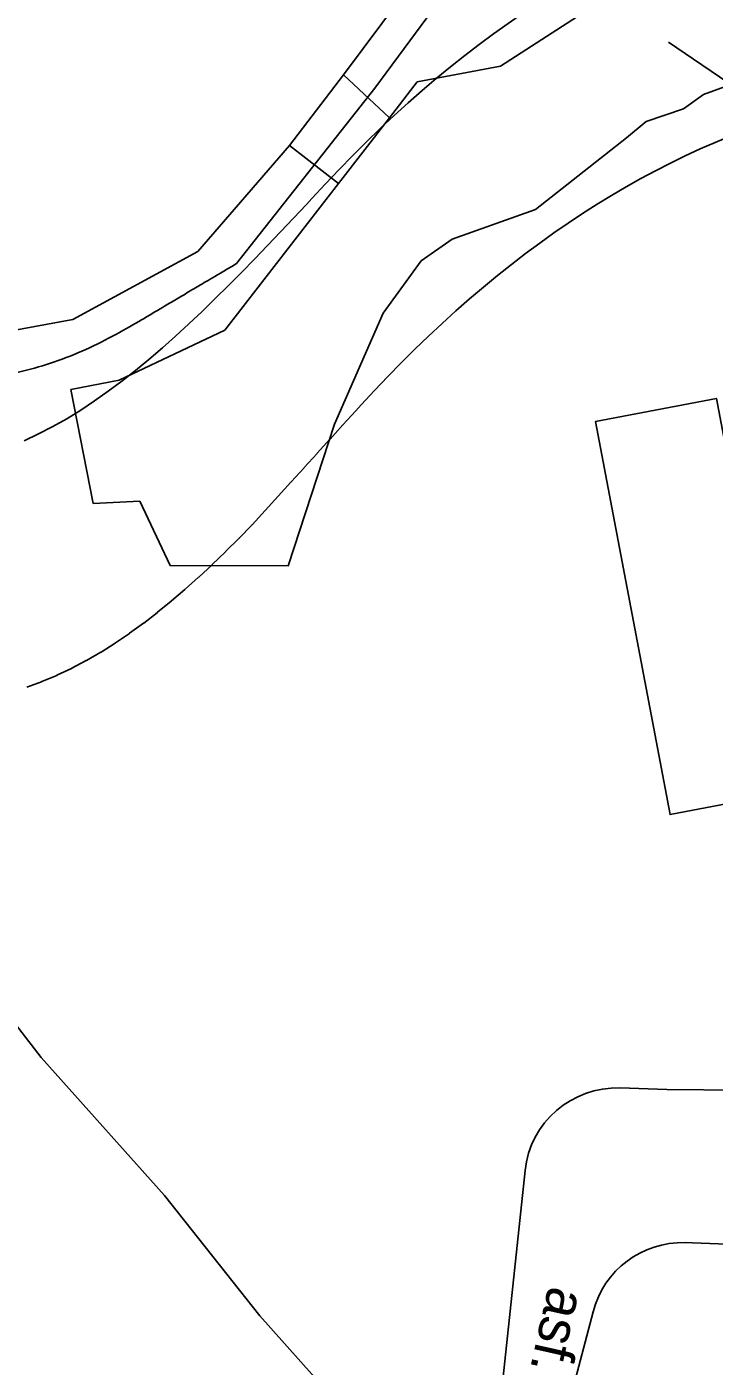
# Model space of a CAD drawing. Extents: x 6541740 to 6566395, y 5525066 to 5530361.
# Drawn here: x 6557403.94 to 6557426.25, y 5526125.72 to 5526169.2 of the extents above; entities that cross this region are included whole.
import ezdxf

# ---------------------------------------------------------------- set-up
doc = ezdxf.new("R2010")
doc.units = 0
for name, color, linetype in [('Domyślna', 7, 'Continuous'), ('ps_wymiarowanie', 7, 'Continuous'), ('TOR_PRZEK_P-teren istniejacy', 7, 'Continuous'), ('TOR_PRZEK_P-uklad odniesienia', 7, 'Continuous'), ('TOR_PS_OPIS_T-symbole geometrii', 7, 'Continuous'), ('TOR_PS_T-rowy otwarte nieumocnione', 7, 'Continuous'), ('TOR_PS_T-wypelnienia', 7, 'Continuous')]:
    doc.layers.add(name, color=color, linetype=linetype)

msp = doc.modelspace()

# ---------------------------------------------------------------- linework, layer by layer
at = {"layer": 'Domyślna'}
for p, q in [((6557413.194, 5526163.62), (6557413.023, 5526163.432)), ((6557413.194, 5526163.62), (6557413.023, 5526163.432)), ((6557414.793, 5526156.921), (6557414.622, 5526156.734)), ((6557414.793, 5526156.921), (6557414.622, 5526156.734))]:
    msp.add_line(p, q, dxfattribs=at)
at = {"layer": 'ps_wymiarowanie'}
for p, q in [((6557412.466, 5526165.343), (6557409.491, 5526161.9)), ((6557412.466, 5526165.343), (6557409.491, 5526161.9)), ((6557409.491, 5526161.9), (6557405.44, 5526159.699)), ((6557409.491, 5526161.9), (6557405.44, 5526159.699)), ((6557386.306, 5526156.188), (6557405.44, 5526159.699)), ((6557386.306, 5526156.188), (6557405.44, 5526159.699)), ((6557406.094, 5526153.721), (6557405.378, 5526157.421)), ((6557406.094, 5526153.721), (6557405.378, 5526157.421)), ((6557424.715, 5526134.701), (6557423.197, 5526134.753)), ((6557424.715, 5526134.701), (6557423.197, 5526134.753)), ((6557427.102, 5526134.683), (6557424.715, 5526134.701)), ((6557427.102, 5526134.683), (6557424.715, 5526134.701)), ((6557420.112, 5526132.071), (6557419.369, 5526125.077)), ((6557420.112, 5526132.071), (6557419.369, 5526125.077)), ((6557425.301, 5526129.733), (6557425.539, 5526129.726)), ((6557425.301, 5526129.733), (6557425.539, 5526129.726)), ((6557425.539, 5526129.726), (6557428.031, 5526129.638)), ((6557425.539, 5526129.726), (6557428.031, 5526129.638)), ((6557421.042, 5526122.606), (6557422.317, 5526127.491)), ((6557421.042, 5526122.606), (6557422.317, 5526127.491))]:
    msp.add_line(p, q, dxfattribs=at)
for points in [[(6557466.511, 5526187.683), (6557465.043, 5526186.988), (6557461.423, 5526185.275), (6557456.522, 5526180.201), (6557454.61, 5526178.451), (6557453.626, 5526177.55), (6557452.528, 5526176.764), (6557450.12, 5526175.708), (6557447.799, 5526174.9), (6557447.318, 5526174.77), (6557446.173, 5526174.319), (6557442.253, 5526172.787), (6557436.476, 5526171.057), (6557431.225, 5526168.935), (6557425.9, 5526167), (6557425.249, 5526166.537), (6557424.035, 5526166.119), (6557423.401, 5526165.589)], [(6557466.511, 5526187.683), (6557465.043, 5526186.988), (6557461.423, 5526185.275), (6557456.522, 5526180.201), (6557454.61, 5526178.451), (6557453.626, 5526177.55), (6557452.528, 5526176.764), (6557450.12, 5526175.708), (6557447.799, 5526174.9), (6557447.318, 5526174.77), (6557446.173, 5526174.319), (6557442.253, 5526172.787), (6557436.476, 5526171.057), (6557431.225, 5526168.935), (6557425.9, 5526167), (6557425.249, 5526166.537), (6557424.035, 5526166.119), (6557423.401, 5526165.589)], [(6557414.217, 5526167.638), (6557417.983, 5526172.683)], [(6557414.217, 5526167.638), (6557417.983, 5526172.683)], [(6557422.48, 5526169.958), (6557419.312, 5526167.917), (6557416.615, 5526167.404), (6557415.709, 5526166.237)], [(6557422.48, 5526169.958), (6557419.312, 5526167.917), (6557416.615, 5526167.404), (6557415.709, 5526166.237)], [(6557412.466, 5526165.343), (6557414.056, 5526164.107), (6557415.709, 5526166.237), (6557414.217, 5526167.638), (6557412.466, 5526165.343)], [(6557412.466, 5526165.343), (6557414.056, 5526164.107), (6557415.709, 5526166.237), (6557414.217, 5526167.638), (6557412.466, 5526165.343)], [(6557423.401, 5526165.589), (6557420.451, 5526163.263), (6557417.742, 5526162.298), (6557416.741, 5526161.601), (6557415.504, 5526159.901), (6557413.933, 5526156.294), (6557412.424, 5526151.696), (6557408.592, 5526151.709), (6557407.609, 5526153.795), (6557406.094, 5526153.721)], [(6557423.401, 5526165.589), (6557420.451, 5526163.263), (6557417.742, 5526162.298), (6557416.741, 5526161.601), (6557415.504, 5526159.901), (6557413.933, 5526156.294), (6557412.424, 5526151.696), (6557408.592, 5526151.709), (6557407.609, 5526153.795), (6557406.094, 5526153.721)], [(6557414.056, 5526164.107), (6557410.366, 5526159.352), (6557406.94, 5526157.723), (6557405.378, 5526157.421)], [(6557414.056, 5526164.107), (6557410.366, 5526159.352), (6557406.94, 5526157.723), (6557405.378, 5526157.421)]]:
    msp.add_lwpolyline(points, dxfattribs=at)
msp.add_lwpolyline([(6557428.739, 5526144.373), (6557424.817, 5526143.629), (6557422.398, 5526156.387), (6557426.32, 5526157.131)], close=True, dxfattribs=at)
msp.add_lwpolyline([(6557428.739, 5526144.373), (6557424.817, 5526143.629), (6557422.398, 5526156.387), (6557426.32, 5526157.131)], close=True, dxfattribs=at)
at = {"layer": 'TOR_PRZEK_P-uklad odniesienia'}
msp.add_line((6557434.581, 5526162.007), (6557424.762, 5526168.697), dxfattribs=at)
msp.add_line((6557434.581, 5526162.007), (6557424.762, 5526168.697), dxfattribs=at)
at = {"layer": 'TOR_PS_OPIS_T-symbole geometrii'}
for p, q in [((6557414.622, 5526156.734), (6557414.202, 5526156.272)), ((6557414.622, 5526156.734), (6557414.202, 5526156.272)), ((6557414.201, 5526156.271), (6557413.782, 5526155.81)), ((6557414.201, 5526156.271), (6557413.782, 5526155.81)), ((6557413.781, 5526155.809), (6557413.364, 5526155.352)), ((6557413.781, 5526155.809), (6557413.364, 5526155.352)), ((6557413.363, 5526155.35), (6557412.94, 5526154.886)), ((6557413.363, 5526155.35), (6557412.94, 5526154.886)), ((6557412.939, 5526154.884), (6557412.518, 5526154.421)), ((6557412.939, 5526154.884), (6557412.518, 5526154.421)), ((6557412.516, 5526154.419), (6557412.097, 5526153.959)), ((6557412.516, 5526154.419), (6557412.097, 5526153.959)), ((6557412.095, 5526153.956), (6557411.676, 5526153.496)), ((6557412.095, 5526153.956), (6557411.676, 5526153.496)), ((6557411.673, 5526153.493), (6557411.255, 5526153.033)), ((6557411.673, 5526153.493), (6557411.255, 5526153.033)), ((6557411.252, 5526153.03), (6557410.828, 5526152.589)), ((6557411.252, 5526153.03), (6557410.828, 5526152.589)), ((6557410.824, 5526152.585), (6557410.396, 5526152.16)), ((6557410.824, 5526152.585), (6557410.396, 5526152.16)), ((6557410.392, 5526152.156), (6557409.961, 5526151.742)), ((6557410.392, 5526152.156), (6557409.961, 5526151.742)), ((6557409.957, 5526151.737), (6557409.524, 5526151.335)), ((6557409.957, 5526151.737), (6557409.524, 5526151.335)), ((6557409.519, 5526151.33), (6557409.083, 5526150.94)), ((6557409.519, 5526151.33), (6557409.083, 5526150.94)), ((6557409.077, 5526150.936), (6557408.638, 5526150.56)), ((6557409.077, 5526150.936), (6557408.638, 5526150.56)), ((6557408.183, 5526150.189), (6557407.737, 5526149.844)), ((6557408.183, 5526150.189), (6557407.737, 5526149.844)), ((6557408.632, 5526150.555), (6557408.189, 5526150.194)), ((6557408.632, 5526150.555), (6557408.189, 5526150.194)), ((6557407.73, 5526149.839), (6557407.28, 5526149.512)), ((6557407.73, 5526149.839), (6557407.28, 5526149.512)), ((6557407.273, 5526149.507), (6557406.818, 5526149.198)), ((6557407.273, 5526149.507), (6557406.818, 5526149.198)), ((6557406.344, 5526148.898), (6557405.881, 5526148.629)), ((6557406.344, 5526148.898), (6557405.881, 5526148.629)), ((6557406.811, 5526149.192), (6557406.352, 5526148.903)), ((6557406.811, 5526149.192), (6557406.352, 5526148.903)), ((6557405.872, 5526148.624), (6557405.405, 5526148.376)), ((6557405.872, 5526148.624), (6557405.405, 5526148.376)), ((6557404.914, 5526148.142), (6557404.437, 5526147.941)), ((6557404.914, 5526148.142), (6557404.437, 5526147.941)), ((6557405.396, 5526148.371), (6557404.924, 5526148.147)), ((6557405.396, 5526148.371), (6557404.924, 5526148.147)), ((6557404.426, 5526147.937), (6557403.944, 5526147.762)), ((6557404.426, 5526147.937), (6557403.944, 5526147.762))]:
    msp.add_line(p, q, dxfattribs=at)
msp.add_lwpolyline([(6557413.023, 5526163.432), (6557412.6, 5526162.985), (6557412.178, 5526162.54), (6557411.755, 5526162.097), (6557411.333, 5526161.658), (6557410.909, 5526161.223), (6557410.485, 5526160.794), (6557410.059, 5526160.372), (6557409.633, 5526159.958), (6557409.204, 5526159.552), (6557408.774, 5526159.157), (6557408.342, 5526158.772), (6557407.908, 5526158.4), (6557407.471, 5526158.04), (6557407.031, 5526157.695), (6557406.589, 5526157.365), (6557406.143, 5526157.051), (6557405.695, 5526156.755), (6557405.242, 5526156.476), (6557404.787, 5526156.218), (6557404.327, 5526155.979), (6557403.863, 5526155.762)], dxfattribs=at)
msp.add_lwpolyline([(6557413.023, 5526163.432), (6557412.6, 5526162.985), (6557412.178, 5526162.54), (6557411.755, 5526162.097), (6557411.333, 5526161.658), (6557410.909, 5526161.223), (6557410.485, 5526160.794), (6557410.059, 5526160.372), (6557409.633, 5526159.958), (6557409.204, 5526159.552), (6557408.774, 5526159.157), (6557408.342, 5526158.772), (6557407.908, 5526158.4), (6557407.471, 5526158.04), (6557407.031, 5526157.695), (6557406.589, 5526157.365), (6557406.143, 5526157.051), (6557405.695, 5526156.755), (6557405.242, 5526156.476), (6557404.787, 5526156.218), (6557404.327, 5526155.979), (6557403.863, 5526155.762)], dxfattribs=at)
for centre, major_axis, start_param, end_param in [((6557505.371, 5525777.489), (-75.146, 396.441), 0.018415, 0.185981), ((6557505.371, 5525777.489), (-75.146, 396.441), 0.018415, 0.185981), ((6557505.371, 5525777.489), (-73.843, 389.563), 0.018415, 0.185981), ((6557505.371, 5525777.489), (-73.843, 389.563), 0.018415, 0.185981), ((6557413.398, 5526159.616), (0.652, -3.439), 0.191609, 0.192157), ((6557413.398, 5526159.616), (0.652, -3.439), 0.191609, 0.192157), ((6557412.978, 5526159.155), (0.652, -3.439), 0.190513, 0.191609), ((6557412.978, 5526159.155), (0.652, -3.439), 0.190513, 0.191609), ((6557412.562, 5526158.697), (0.652, -3.439), 0.18887, 0.190513), ((6557412.562, 5526158.697), (0.652, -3.439), 0.18887, 0.190513), ((6557412.139, 5526158.233), (0.652, -3.439), 0.186679, 0.18887), ((6557412.139, 5526158.233), (0.652, -3.439), 0.186679, 0.18887), ((6557411.718, 5526157.77), (0.652, -3.439), 0.183939, 0.186679), ((6557411.718, 5526157.77), (0.652, -3.439), 0.183939, 0.186679), ((6557411.299, 5526157.31), (0.652, -3.439), 0.180652, 0.183939), ((6557411.299, 5526157.31), (0.652, -3.439), 0.180652, 0.183939), ((6557410.88, 5526156.849), (0.652, -3.439), 0.176817, 0.180652), ((6557410.88, 5526156.849), (0.652, -3.439), 0.176817, 0.180652), ((6557410.462, 5526156.39), (0.652, -3.439), 0.172435, 0.176817), ((6557410.462, 5526156.39), (0.652, -3.439), 0.172435, 0.176817), ((6557410.038, 5526155.949), (0.652, -3.439), 0.167504, 0.172435), ((6557410.038, 5526155.949), (0.652, -3.439), 0.167504, 0.172435), ((6557409.61, 5526155.523), (0.652, -3.439), 0.162026, 0.167504), ((6557409.61, 5526155.523), (0.652, -3.439), 0.162026, 0.167504), ((6557409.179, 5526155.109), (0.652, -3.439), 0.155999, 0.162026), ((6557409.179, 5526155.109), (0.652, -3.439), 0.155999, 0.162026), ((6557408.746, 5526154.706), (0.652, -3.439), 0.149425, 0.155999), ((6557408.746, 5526154.706), (0.652, -3.439), 0.149425, 0.155999), ((6557408.31, 5526154.317), (0.652, -3.439), 0.142303, 0.149425), ((6557408.31, 5526154.317), (0.652, -3.439), 0.142303, 0.149425), ((6557407.428, 5526153.58), (0.652, -3.439), 0.126416, 0.134633), ((6557407.428, 5526153.58), (0.652, -3.439), 0.126416, 0.134633), ((6557407.871, 5526153.941), (0.652, -3.439), 0.134633, 0.142303), ((6557407.871, 5526153.941), (0.652, -3.439), 0.134633, 0.142303), ((6557406.982, 5526153.235), (0.652, -3.439), 0.11765, 0.126416), ((6557406.982, 5526153.235), (0.652, -3.439), 0.11765, 0.126416), ((6557406.532, 5526152.908), (0.652, -3.439), 0.108337, 0.11765), ((6557406.532, 5526152.908), (0.652, -3.439), 0.108337, 0.11765), ((6557405.619, 5526152.309), (0.652, -3.439), 0.088067, 0.098476), ((6557405.619, 5526152.309), (0.652, -3.439), 0.088067, 0.098476), ((6557406.077, 5526152.599), (0.652, -3.439), 0.098476, 0.108337), ((6557406.077, 5526152.599), (0.652, -3.439), 0.098476, 0.108337), ((6557405.156, 5526152.04), (0.652, -3.439), 0.07711, 0.088067), ((6557405.156, 5526152.04), (0.652, -3.439), 0.07711, 0.088067), ((6557404.217, 5526151.567), (0.652, -3.439), 0.053553, 0.065606), ((6557404.217, 5526151.567), (0.652, -3.439), 0.053553, 0.065606), ((6557404.689, 5526151.792), (0.652, -3.439), 0.065606, 0.07711), ((6557404.689, 5526151.792), (0.652, -3.439), 0.065606, 0.07711), ((6557403.74, 5526151.367), (0.652, -3.439), 0.040948, 0.053553), ((6557403.74, 5526151.367), (0.652, -3.439), 0.040948, 0.053553)]:
    msp.add_ellipse(centre, major_axis=major_axis, ratio=0.25, start_param=start_param, end_param=end_param, dxfattribs=at)
at = {"layer": 'TOR_PS_T-rowy otwarte nieumocnione'}
for points in [[(6557410.752, 5526161.512), (6557415.237, 5526167.201), (6557419.016, 5526172.319), (6557421.604, 5526175.738), (6557422.766, 5526177.272), (6557422.901, 5526177.451)], [(6557410.752, 5526161.512), (6557415.237, 5526167.201), (6557419.016, 5526172.319), (6557421.604, 5526175.738), (6557422.766, 5526177.272), (6557422.901, 5526177.451)], [(6557422.901, 5526177.451), (6557422.766, 5526177.272), (6557421.604, 5526175.738), (6557419.016, 5526172.319), (6557415.237, 5526167.201), (6557410.752, 5526161.512)], [(6557410.752, 5526161.512), (6557415.237, 5526167.201), (6557419.016, 5526172.319), (6557421.604, 5526175.738), (6557422.766, 5526177.272), (6557422.901, 5526177.451)], [(6557410.752, 5526161.512), (6557415.237, 5526167.201), (6557419.016, 5526172.319), (6557421.604, 5526175.738), (6557422.766, 5526177.272), (6557422.901, 5526177.451)], [(6557422.901, 5526177.451), (6557422.766, 5526177.272), (6557421.604, 5526175.738), (6557419.016, 5526172.319), (6557415.237, 5526167.201), (6557410.752, 5526161.512)], [(6557419.616, 5526118.832), (6557416.122, 5526122.179), (6557411.509, 5526127.36), (6557408.417, 5526131.265), (6557404.415, 5526135.744), (6557397.189, 5526145.106)], [(6557419.616, 5526118.832), (6557416.122, 5526122.179), (6557411.509, 5526127.36), (6557408.417, 5526131.265), (6557404.415, 5526135.744), (6557397.189, 5526145.106)], [(6557419.616, 5526118.832), (6557416.122, 5526122.179), (6557411.509, 5526127.36), (6557408.417, 5526131.265), (6557404.415, 5526135.744), (6557397.189, 5526145.106)], [(6557419.616, 5526118.832), (6557416.122, 5526122.179), (6557411.509, 5526127.36), (6557408.417, 5526131.265), (6557404.415, 5526135.744), (6557397.189, 5526145.106)]]:
    msp.add_lwpolyline(points, dxfattribs=at)
msp.add_open_spline([(6557392.659, 5526156.002), (6557395.76, 5526156.551), (6557398.86, 5526157.099), (6557401.961, 5526157.648), (6557404.075, 5526158.022), (6557406.121, 5526158.769), (6557408.077, 5526159.928), (6557408.523, 5526160.192), (6557408.969, 5526160.456), (6557409.415, 5526160.72), (6557409.861, 5526160.984), (6557410.306, 5526161.248), (6557410.752, 5526161.512)], degree=3, dxfattribs=at)
msp.add_open_spline([(6557392.659, 5526156.002), (6557395.76, 5526156.551), (6557398.86, 5526157.099), (6557401.961, 5526157.648), (6557404.075, 5526158.022), (6557406.121, 5526158.769), (6557408.077, 5526159.928), (6557408.523, 5526160.192), (6557408.969, 5526160.456), (6557409.415, 5526160.72), (6557409.861, 5526160.984), (6557410.306, 5526161.248), (6557410.752, 5526161.512)], degree=3, dxfattribs=at)
msp.add_open_spline([(6557392.659, 5526156.002), (6557395.76, 5526156.551), (6557398.86, 5526157.099), (6557401.961, 5526157.648), (6557404.075, 5526158.022), (6557406.121, 5526158.769), (6557408.077, 5526159.928), (6557408.523, 5526160.192), (6557408.969, 5526160.456), (6557409.415, 5526160.72), (6557409.861, 5526160.984), (6557410.306, 5526161.248), (6557410.752, 5526161.512)], degree=3, dxfattribs=at)
msp.add_open_spline([(6557392.659, 5526156.002), (6557395.76, 5526156.551), (6557398.86, 5526157.099), (6557401.961, 5526157.648), (6557404.075, 5526158.022), (6557406.121, 5526158.769), (6557408.077, 5526159.928), (6557408.523, 5526160.192), (6557408.969, 5526160.456), (6557409.415, 5526160.72), (6557409.861, 5526160.984), (6557410.306, 5526161.248), (6557410.752, 5526161.512)], degree=3, dxfattribs=at)
msp.add_open_spline([(6557392.659, 5526156.002), (6557395.76, 5526156.551), (6557398.86, 5526157.099), (6557401.961, 5526157.648), (6557404.075, 5526158.022), (6557406.121, 5526158.769), (6557408.077, 5526159.928), (6557408.523, 5526160.192), (6557408.969, 5526160.456), (6557409.415, 5526160.72), (6557409.861, 5526160.984), (6557410.306, 5526161.248), (6557410.752, 5526161.512)], degree=3, dxfattribs=at)
msp.add_open_spline([(6557392.659, 5526156.002), (6557395.76, 5526156.551), (6557398.86, 5526157.099), (6557401.961, 5526157.648), (6557404.075, 5526158.022), (6557406.121, 5526158.769), (6557408.077, 5526159.928), (6557408.523, 5526160.192), (6557408.969, 5526160.456), (6557409.415, 5526160.72), (6557409.861, 5526160.984), (6557410.306, 5526161.248), (6557410.752, 5526161.512)], degree=3, dxfattribs=at)
at = {"layer": 'TOR_PS_T-wypelnienia'}
for centre, start, end in [((6557423.095, 5526131.755), 88.0416, 173.941), ((6557423.095, 5526131.755), 88.0416, 173.941), ((6557425.22, 5526126.734), 88.447, 165.3724), ((6557425.22, 5526126.734), 88.447, 165.3724)]:
    msp.add_arc(centre, 3, start, end, dxfattribs=at)

# ---------------------------------------------------------------- texts
at = {"layer": 'TOR_PRZEK_P-teren istniejacy'}
msp.add_text('asf.', height=1.3021, rotation=257.3504, dxfattribs=at).set_placement((6557420.883, 5526128.368))
msp.add_text('asf.', height=1.3021, rotation=257.3504, dxfattribs=at).set_placement((6557420.883, 5526128.368))

doc.saveas('drawing.dxf')
